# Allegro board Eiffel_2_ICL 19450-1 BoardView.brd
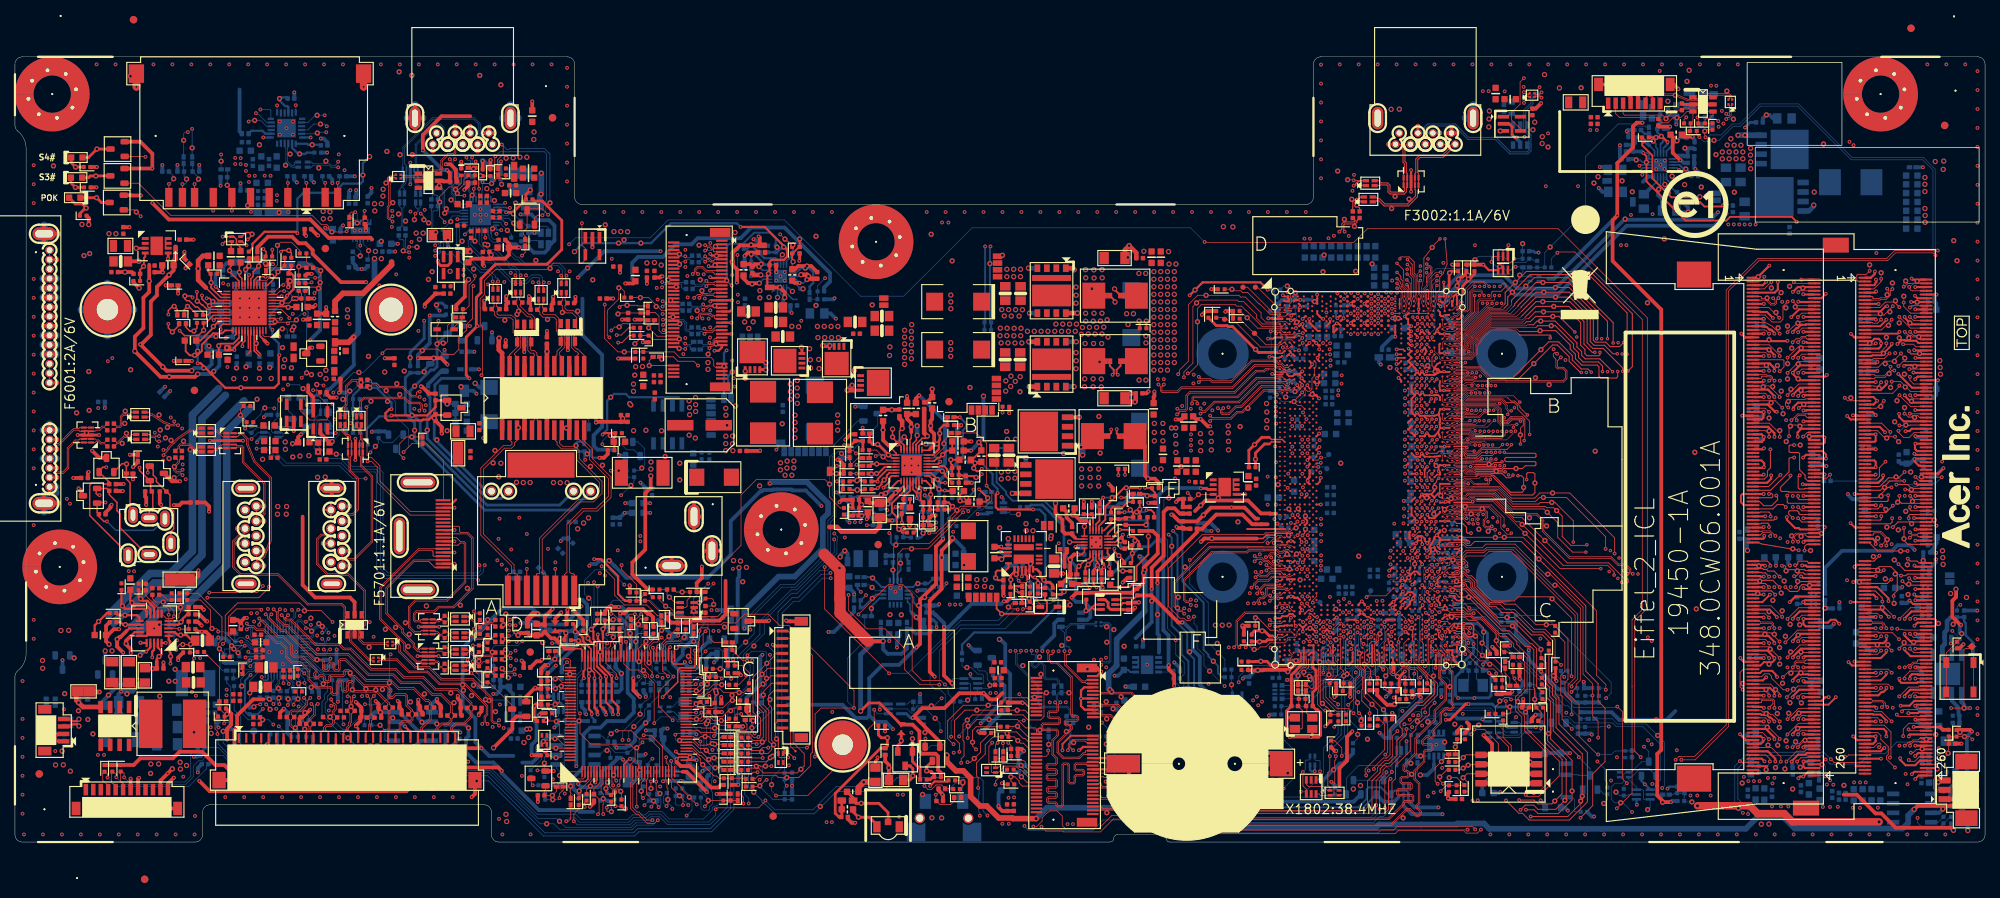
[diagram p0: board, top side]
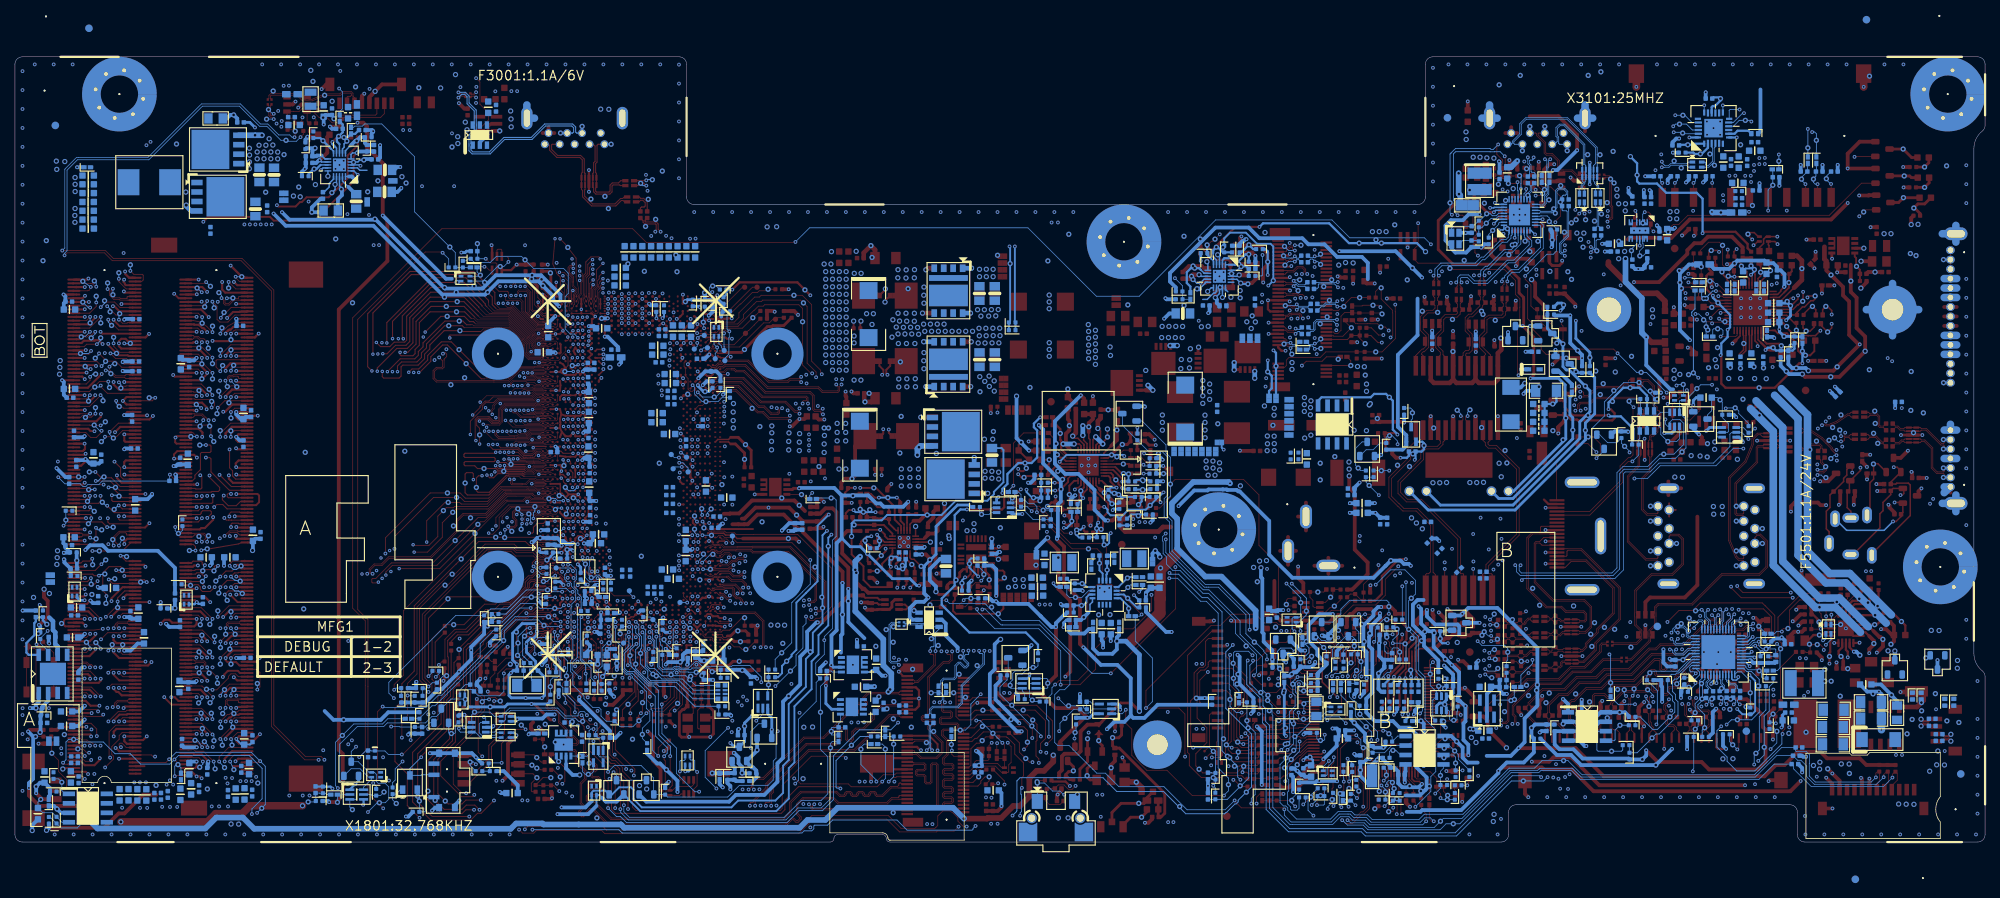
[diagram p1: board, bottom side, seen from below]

Outline 264 x 105.3 mm; copper layers: TOP, L2GND, L3, L4, L5GND, BOTTOM. Coordinates in mm from the lower left corner of the outline.
Outline path: 0,104.3 0,96.12 arc(0.1,95.69) 0.37,95.34 arc(1.2,94.3) 1.5,93 1.5,25.3 arc(1.2,24) 0.37,22.96 arc(0.1,22.61) 0,22.18 0,1 arc(0.29,0.29) 1,0 24.15,0 arc(24.86,0.29) 25.15,1 25.15,4 arc(25.44,4.71) 26.15,5 62.85,5 arc(63.56,4.71) 63.85,4 63.85,1 arc(64.14,0.29) 64.85,0 146.75,0 arc(147.1,0.15) 147.25,0.5 arc(147.4,0.85) 147.75,1 153.75,1 arc(154.1,0.85) 154.25,0.5 arc(154.4,0.15) 154.75,0 263,0 arc(263.71,0.29) 264,1 264,104.3 arc(263.71,105.01) 263,105.3 175,105.3 arc(174.29,105.01) 174,104.3 174,86.5 arc(173.71,85.79) 173,85.5 76,85.5 arc(75.29,85.79) 75,86.5 75,104.3 arc(74.71,105.01) 74,105.3 1,105.3 arc(0.29,105.01) 0,104.3

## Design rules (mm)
constraint set DEFAULT: min track width 0.127
net group AUD_W15_S10: nets CPVDD CPVEE
net group FAN_PWR_W20: nets FAN5V_OUT FAN5V_OUT_CONN
net group LPSS_UART2: nets LPSS_UART2_RXD LPSS_UART2_TXD
net group PCIE_RCOMP: nets PCIE_RCOMPN PCIE_RCOMPP
net group POWER_15_10: nets PROCHOT#_CPU PWR_VCORE_VCCST
net group POWER_20_20: nets PWR_VNN1D05V_BOOTA PWR_VNN1D05V_BOOTB
net group POWER_30_10: nets 3D3V_CARD 3D3V_S5_SPI
net group POWER_40_10: nets 3D3V_SIO_AVCC3 PWRLED_CON_5V
net group PWR_VCCAUX: nets PWR_VCCAUX_FSWEL PWR_VCCAUX_VOUT
net group RCOMP_W30_S12: nets EMMC_RCOMP XCLK_BIASREF
net group RTC: nets RTCRST_ON RTCRST_ON_R
net group SD_CLK: nets SD_CLK SD_CLK_1
net group TCRCOMP: nets TCRCOMP_DN TCRCOMP_DP
net group USB2_COMP: nets USB2_COMP USB_VBUSSENSE
net group 0D85V_S5: nets 0D85V_S5_VCCLDOSTD_OUT VCCIN_AUX_VID0 VCCIN_AUX_VID1 VCCST_OVERRIDE VCCST_OVERRIDE_N VCCSTPWRGOOD_TCSS
net group 50R_CNV_M_1: nets BT_PCMFRM_RSTN BT_PCMOUT_CLKREQ0 CNV_WT_RCOMP GPP_A8_SFRM GPP_A9_CLKREQ0
net group 50R_CNVI_W4_S20: nets CNV_BRI_DT CNV_BRI_DT_R CNV_BRI_RSP CNV_BRI_RSP_R CNV_RGI_DT CNV_RGI_DT_R CNV_RGI_RSP CNV_RGI_RSP_R
net group AUD_ANALOG_W8_S15: nets 3V_MIC2V AUD_HP1_JACK_L1 AUD_HP1_JACK_L2 AUD_HP1_JACK_L2_R AUD_HP1_JACK_R1 AUD_HP1_JACK_R2 AUD_HP1_JACK_R2_R AUD_HP1_JD# AUD_HP1_JD#_TYPE AUD_SENSE_A LINE1_L LINE1_R LINE1_VREFO_L LINE1_VREFO_R RING2 SELEEVE
net group AUD_DMIC_W4_S8: nets CODEC_I2C_SCL_DMIC_L CODEC_I2C_SCL_DMIC_R CODEC_I2C_SDA_DMIC_L CODEC_I2C_SDA_DMIC_R DMIC1_DATA_CON DMIC_CLK_CON DMIC_CLK_DMIC1 DMIC_DATA_DMIC1
net group AUD_W10_S10: nets CBN CBP LDO1_CAP LDO2_CAP LDO3_CAP MIC_CAP
net group AUD_W25_S8: nets AUDIO_VREF
net group CFG_RCOMP: nets CFG_RCOMP
net group CHGR_PSYS_IMVP: nets CHGR_PSYS_IMVP
net group CPU_POPI_RCOMP: nets CPU_POPI_RCOMP
net group CSI_RCOMP: nets CSI_RCOMP
net group DDR4_A_CMD: nets M_A_A0 M_A_A1 M_A_A2 M_A_A3 M_A_A4 M_A_A5 M_A_A6 M_A_A7 M_A_A8 M_A_A9 M_A_A10 M_A_A11 M_A_A12 M_A_A13 M_A_A14 M_A_A15 M_A_A16
net group DDR4_A_CNT: nets M_A_ACT_N M_A_ALERT_N M_A_BA0 M_A_BA1 M_A_BG0 M_A_BG1 M_A_CKE0 M_A_CKE1 M_A_CS#0 M_A_CS#1 M_A_ODT0 M_A_ODT1 M_A_PARITY
net group DDR4_A_DATA0: nets M_A_DQ0 M_A_DQ1 M_A_DQ2 M_A_DQ3 M_A_DQ4 M_A_DQ5 M_A_DQ6 M_A_DQ7
net group DDR4_A_DATA1: nets M_A_DQ8 M_A_DQ9 M_A_DQ10 M_A_DQ11 M_A_DQ12 M_A_DQ13 M_A_DQ14 M_A_DQ15
net group DDR4_A_DATA2: nets M_A_DQ16 M_A_DQ17 M_A_DQ18 M_A_DQ19 M_A_DQ20 M_A_DQ21 M_A_DQ22 M_A_DQ23
net group DDR4_A_DATA3: nets M_A_DQ24 M_A_DQ25 M_A_DQ26 M_A_DQ27 M_A_DQ28 M_A_DQ29 M_A_DQ30 M_A_DQ31
net group DDR4_A_DATA4: nets M_A_DQ32 M_A_DQ33 M_A_DQ34 M_A_DQ35 M_A_DQ36 M_A_DQ37 M_A_DQ38 M_A_DQ39
net group DDR4_A_DATA5: nets M_A_DQ40 M_A_DQ41 M_A_DQ42 M_A_DQ43 M_A_DQ44 M_A_DQ45 M_A_DQ46 M_A_DQ47
net group DDR4_A_DATA6: nets M_A_DQ48 M_A_DQ49 M_A_DQ50 M_A_DQ51 M_A_DQ52 M_A_DQ53 M_A_DQ54 M_A_DQ55
net group DDR4_A_DATA7: nets M_A_DQ56 M_A_DQ57 M_A_DQ58 M_A_DQ59 M_A_DQ60 M_A_DQ61 M_A_DQ62 M_A_DQ63
net group DDR4_B_CMD: nets M_B_A0 M_B_A1 M_B_A2 M_B_A3 M_B_A4 M_B_A5 M_B_A6 M_B_A7 M_B_A8 M_B_A9 M_B_A10 M_B_A11 M_B_A12 M_B_A13 M_B_A14 M_B_A15 M_B_A16
net group DDR4_B_CNT: nets M_B_ACT_N M_B_ALERT_N M_B_BA0 M_B_BA1 M_B_BG0 M_B_BG1 M_B_CKE0 M_B_CKE1 M_B_CS#0 M_B_CS#1 M_B_ODT0 M_B_ODT1 M_B_PARITY
net group DDR4_B_DATA0: nets M_B_DQ0 M_B_DQ1 M_B_DQ2 M_B_DQ3 M_B_DQ4 M_B_DQ5 M_B_DQ6 M_B_DQ7
net group DDR4_B_DATA1: nets M_B_DQ8 M_B_DQ9 M_B_DQ10 M_B_DQ11 M_B_DQ12 M_B_DQ13 M_B_DQ14 M_B_DQ15
net group DDR4_B_DATA2: nets M_B_DQ16 M_B_DQ17 M_B_DQ18 M_B_DQ19 M_B_DQ20 M_B_DQ21 M_B_DQ22 M_B_DQ23
net group DDR4_B_DATA3: nets M_B_DQ24 M_B_DQ25 M_B_DQ26 M_B_DQ27 M_B_DQ28 M_B_DQ29 M_B_DQ30 M_B_DQ31
net group DDR4_B_DATA4: nets M_B_DQ32 M_B_DQ33 M_B_DQ34 M_B_DQ35 M_B_DQ36 M_B_DQ37 M_B_DQ38 M_B_DQ39
net group DDR4_B_DATA5: nets M_B_DQ40 M_B_DQ41 M_B_DQ42 M_B_DQ43 M_B_DQ44 M_B_DQ45 M_B_DQ46 M_B_DQ47
net group DDR4_B_DATA6: nets M_B_DQ48 M_B_DQ49 M_B_DQ50 M_B_DQ51 M_B_DQ52 M_B_DQ53 M_B_DQ54 M_B_DQ55
net group DDR4_B_DATA7: nets M_B_DQ56 M_B_DQ57 M_B_DQ58 M_B_DQ59 M_B_DQ60 M_B_DQ61 M_B_DQ62 M_B_DQ63
net group DDR4_RCOMP_15: nets SM_RCOMP_0 SM_RCOMP_1 SM_RCOMP_2
net group DISP_RCOMP: nets DISP_RCOMP
net group EC_VFSPI: nets EC_VFSPI
net group ECIO_HW_S10: nets SIO_VREF SYS_TMPIN1 VRD_TMPIN2
net group ECIO_W4_S10: nets E51_RXD E51_TXD E51_TXD_EC E51_TXD_R EAPD# LDRQ# PB_IN_N_1 PWRBTN# PWRBTN#_1 PWRBTN_IN SIO_AUDIO_MUTE SIO_CE_N SIO_CLK_DB SIO_DAT_DB SIO_HOLD# SIO_SCK SIO_SCK_R SIO_SI SIO_SO SIO_WP# SIO_WRST#
net group ESPI_AD_CPU: nets ESPI_CON_ALERT# ESPI_CPU_CLK ESPI_CPU_CLK_DBG ESPI_CPU_CLK_EC ESPI_CPU_CS# ESPI_CPU_CS#_DB ESPI_CPU_CS#_EC ESPI_CPU_IO0 ESPI_CPU_IO0_DB ESPI_CPU_IO0_EC ESPI_CPU_IO1 ESPI_CPU_IO1_DB ESPI_CPU_IO1_EC ESPI_CPU_IO2 ESPI_CPU_IO2_DB ESPI_CPU_IO2_EC ESPI_CPU_IO3 ESPI_CPU_IO3_DB ESPI_CPU_IO3_EC ESPI_CPU_RST# ESPI_EC_ALERT# ESPI_EC_ALERT#_CPU
net group FAN_CTRL_W4_S15: nets CPU_FAN_CTRL CPU_FAN_CTRL_SIO CPU_FAN_TACH_SIO
net group HDA_W5_S10: nets HDA_BITCLK_CODEC HDA_BITCLK_CPU HDA_RST_N_CODEC HDA_RST_N_CODEC_R HDA_RST_N_CPU HDA_SDIN0_CODEC HDA_SDIN0_CPU HDA_SDOUT_CODEC HDA_SDOUT_CPU HDA_SPKR HDA_SYNC_CODEC HDA_SYNC_CPU
net group HDMI_DDC_W4_S10: nets HDMI1_DDCCLK_CON HDMI1_DDCDATA_CON HDMI_SCL_CPU HDMI_SDA_CPU
net group LAN_CLK: nets LAN_XTAL1 LAN_XTAL2 LAN_XTAL2_R
net group LAN_XF: nets XRF_TDC1
net group LED_W15_S10: nets LAN_EESK LAN_LED_ACTIVE LAN_LINK_100 LAN_LINK_1000 LAN_LINK_N LED2_N LED2_P LED9_N LED9_P LED10_N LED10_P PWRLED_CON SPEED_100_L1 SPEED_1000_L1 SUSLED_1 SUSLED_2 SUSLED_CON SUSLED_CON_OR SUSLED_CON_P1 V_5_LED
net group LPC_CLK: nets SIO_PCICLK
net group LVDS_W4_S8: nets BKLT_ADJ BKLT_ADJ_PWM BKLT_EN BKLT_EN_EC BKLT_EN_ENA DP_REXT DP_VARY_BL_R LCD_5V_ON1 MODE_CFG0 MODE_CFG1 PS8625_BKLT_EN PS8625_BKLT_PWM PS8625_LCD_PW_EN RTL_ISOLATE_N TEST_MODE
net group MISC_4_9: nets LAN_WAKE# LAN_WAKE#_R LAN_WAKEB MINI1_WAKE# PCIE_WAKE# SSD_WAKE# THERMAL_SHUT#
net group OCP: nets 65W_OCP IMON_VIN IMON_VIN_N IMON_VIN_P IMON_VOUT IMON_VOUT_Q5 IMON_VOUT_R1 IMON_VOUT_R1_G PSYS
net group OTHER_4: nets BIOS_REC D4302_PIN3 DBG_PMODE GSPI_MOSI PCH_PWROK_R PCH_THERMTRIP PM_BATLOW# PMCALERT# PROC_TCK PROC_TDI PROC_TMS PROC_TRST# RSVD RTC_INTRUDER# SATAXPCIE1 SVID_ALERT#_CPU_R
net group PANEL_4_10: nets PWR_ID0 PWR_ID1 PWR_ID2
net group PCH_RCOMP: nets PCH_OPI_RCOMP
net group POWER_10_10: nets PWR_1D8V_VFB PWR_1D8V_VFB_A PWR_3D3V_FB2_A PWR_VCCAUX_PG PWR_VCORE_CLK PWR_VCORE_DATA PWR_VCORE_FB PWR_VCORE_IMON PWR_VCORE_PSYS PWR_VCORE_SET1 PWR_VCORE_SET1_A PWR_VCORE_SET1_B PWR_VCORE_SET2 PWR_VCORE_SET2_A PWR_VCORE_SET2_B PWR_VCORE_SET3 PWR_VCORE_SET3_A PWR_VCORE_SET3_B PWR_VCORE_VIN PWR_VNN1D05V_PG1 PWR_VNN1D05V_PG2 PWR_VNN1D05V_VID
net group POWER_10_15: nets PWR_1D8V_PFM PWR_1D8V_SS PWR_VCCAUX_COMP PWR_VCCAUX_COMPA PWR_VCCAUX_COMPB PWR_VCCAUX_CS_DIS PWR_VCCAUX_FB PWR_VCCAUX_ISENSEP PWR_VCCAUX_NTC PWR_VCCAUX_VID0 PWR_VCCAUX_VID1 PWR_VCCAUX_VOUTA PWR_VCCAUX_VSYS PWR_VCORE_ISEN1N PWR_VCORE_ISEN1P PWR_VCORE_ISEN1P_B PWR_VCORE_ISEN2N PWR_VCORE_ISEN2P PWR_VCORE_ISEN2P_B PWR_VCORE_NTC1N PWR_VCORE_NTC1N_A PWR_VCORE_NTC1P PWR_VCORE_RGND PWR_VCORE_TSEN PWR_VCORE_TSEN_A PWR_VCORE_TSEN_A_A PWR_VCORE_VREF PWR_VCORE_VREF_A PWR_VCORE_VSEN PWR_VNN1D05V_FB2 PWR_VNN1D05V_VOUT1
net group POWER_12_10: nets 1D8V_AUDIO_S0 1D8V_S5_PWRGD 3D3V_SB_SYS 5V_AUX_S5 19V_ADP_GATE HDMI_SCL_R HDMI_SDA_R PROCHOT#_CPU_R PWR_1D8V_PG PWR_2D5V_EN PWR_3D3V_5V_PG PWR_3D3V_CS2 PWR_5V_CS1 PWR_ISET PWR_LPF PWR_MCT1_R PWR_RT PWR_SSTCMP PWR_SSTCMP_1 PWR_STATUS PWR_VCCAUX_EN PWR_VCORE_COMP PWR_VCORE_VR_READY PWR_VDDQ_CS PWR_VDDQ_EN PWR_VDDQ_PG PWR_VDDQ_TON PWR_VTT_EN VCORE_PWRGD
net group POWER_20_10: nets 1D2V_VCCPLL_OC 1D05V_S5_BYPASS 1D05V_VCCIO_OUT 1D05V_VCCSTG_OUT_FUSE 1D05V_VCCSTG_OUT_LGC 1D05V_VNN_BYPASS 1D8V_S5_CLKLDO 1D8V_S5_CLKLDO_R 1D24V_S5_VCCDPHY_OUT 3D3V_RTC_PWR 3D3V_RTC_VCC 3D3V_SB_RTC 3D3V_VBAT_SIO 5V_PVDD2 5V_STB 5V_SUS1 19V_BOOST_SNB PWR_1D8V_TON PWR_3D3V_BOOT2 PWR_3D3V_BOOT2_A PWR_5V_BOOT1 PWR_5V_BOOT1_A PWR_DDR_SN PWR_VCCAUX_PVCC PWR_VCCAUX_VCC PWR_VCORE_BOOTA PWR_VCORE_BOOTA_A PWR_VCORE_BOOTB PWR_VCORE_BOOTB_A PWR_VCORE_VCC PWR_VDDQ_BOOT PWR_VDDQ_BOOT_A PWR_VNN1D05V_VCC
net group POWER_25_20: nets 19V_BOOST_LDR 19V_BOOST_LDR_R PWR_VCCAUX_LG PWR_VCORE_LGA PWR_VCORE_LGB
net group POWER_30_20: nets PWR_1D8V_BT
net group POWER_30_30: nets PWR_VDDQ_LG
net group POWER_40_12: nets V_SMA_VREF_CA V_SMA_VREF_CA_C V_SMB_VREF_CA V_SMB_VREF_CA_C
net group POWER_80: nets 1D05V_S5_VCCDSW_OUT
net group POWER_300: nets PWR_2D5V_FB PWR_3D3V_FB2 PWR_5V_BYP1 PWR_5V_FB1 PWR_5V_FB1_A PWR_5V_LDO5 PWR_VCORE_PVCC PWR_VDDQ_FB PWR_VDDQ_VDD PWR_VDDQ_VDDQ PWR_VDDQ_VID PWR_VDDQ_VTTREF
net group POWER_400: nets 3D3V_DB1
net group PWR_5V_3D3V_EN: nets 1D8V_S0_EN PWR_3D3V_EN2 PWR_5V_EN1
net group PWR_20_20: nets 19V_BOOST_ISW 19V_DCBATOUT_LCD_VIN PWR_ISEN1 PWR_ISEN2 PWR_ISEN3 PWR_ISEN4 PWR_VREF
net group PWR_VNN1D05V_BOOT: nets PWR_VCCAUX_BOOTA PWR_VNN1D05V_BOOTA_A PWR_VNN1D05V_BOOTB_A
net group SD_W4_S10: nets SD_CD_N# SD_CMD SD_DATA0 SD_DATA0_1 SD_DATA1 SD_DATA1_1 SD_DATA2 SD_DATA3 SD_WP
net group SD_W12_S12: nets AV18 CR_PE_REXT SD3_RCOMP SDREG
net group SEQUENCE_W4_S10: nets 1D05V_VCCST_EN 1D05V_VCCSTG_EN 1D05V_VCCSTG_EN_R 1D8V_FCH_C10_EN 2D5V_S3_EN 2D5V_S3_EN_EC 2D5V_S3_PWRGD 3V_5V_PWRGD 5V_3D3V_S0_ON 5V_FANCTL1_FSM# AC_PRESENT ALL_SYS_PWRGD AUDIO_PC_BEEP AUDIO_PC_BEEP255 AUDIO_PC_BEEP256 AUDIO_PC_BEEP_R BT_DISABLE_N CNVI_EN# CPU_C10_GATE# CPU_C10_GATE#_EC DDR_VTT_CNTL_L1 DDR_VTT_CNTL_L2 DDR_VTT_CNTL_L3 DEVSLP2 DEVSLP2_CON EC_AUDIO_MUTE EC_DTR2#_PH EC_EUP EC_EUP_EN EC_EUP_EN# EC_SCI# EC_SMI# EC_SMI#_R ECIO_RSMRST# EDP_BLCTRL_CPU EDP_BLEN_CPU EDP_HPD_CPU EDP_VDDEN_CPU EUP_DSW_SEL EXT_PWR_GATE# EXT_PWR_GATE#_R H_CATERR# H_RCIN# HDMI1_HPD_C HDMI1_HPD_CON HDMI1_LS_R HDMI_DET_CPU HPGP_M2_SATA_DET# ICH_RSMRST_N_R INPUT3VSEL JP1 KBDATA LAN_CLKREQ_CPU_N LAN_CLKREQ_CPU_N_C LAN_RSET LPC_PME# LVDS1_PIN4_PD ME_CNTL1 ME_CNTL2 ME_UNLOCK MINI_CLKREQ#_WLAN_C PCH_D1_SST PCH_DPWROK PCH_DPWROK_EC PCH_DPWROK_R PCH_JTAG_TCK PCH_JTAG_TDO PCH_PWROK PCH_PWROK_C_1 PCH_PWROK_C_2 PCH_PWROK_C_3 PCH_RTCRST_DOWN PCIRST1# PCIRST2# PCIRST_LAN# PECI_EC PECI_EC_R PLT_RST# PLT_RST_N_SSD PLT_WLAN_RST# PLTRST_LAN_N PLTRST_N_SIO PLTRST_SSD PM_CLKRUN#_EC PM_CLKRUN#_EC_R PM_PWRBTN# PM_RSMRST# PM_SLP_S0# PM_SLP_S3# PM_SLP_S3_N PM_SLP_S4# PM_SLP_S4_N PM_SLP_SUSB# PM_SLP_SUSB#_ECIO PROCHOT_N_CPU PROCHOT_N_EC PROCHOT_N_OCP PROCHOT_N_OCP_R PS8625_HPD_R PWR_1D05V_EN PWR_1D8V_EN PWR_1D8V_EN_R PWR_VCORE_VR_EN PWR_VNN_EN PWRGD_PS_L PWRGD_PS_L1 PWROK3_1 PWROK3_1_R Q4002_2 Q4002_6 Q9639_AB_EC RSMRST_PWRGD# RSMRST_PWRGD#_ECIO RTC_DET# RTC_RST# RTC_RST#_R SA1_DIMB SE_BJT_B1 SE_BJT_B2 SE_BJT_B3 SE_VPP_EN_B SE_VTT_EN SIO_ATXPG SIO_BOARD_ID1 SIO_BOARD_ID2 SIO_BOARD_ID3 SIO_COPEN# SIO_DEBUG_RX SIO_DEBUG_TX SIO_GP17 SIO_K8PWR_EN SIO_PSON_N SIO_PSON_N_1 SM_DRAMRST# SM_DRAMRST#_CPU SM_PGCNTL SML1ALERT SRTC_RST# SSD1_CLKREQ_CPU_N SSD_CLKREQ# SUSLED_N SW_ON_N_SIO SYS_PWROK SYS_RESET# TBT_LSX0_RXD TBT_LSX1_RXD TBT_LSX2_RXD TBT_LSX3_RXD TP_CPU_PWRGD TP_DA11 TP_ISP_0 TP_ISP_1 TP_ISP_TRIG_0 TP_ISP_TRIG_1 TP_PCH_IST_1 TP_PROC_SELECT# TP_SKTOCC# TS#_DIMM1_0 TS#_DIMM1_1 USB_EN USB_EN_FRONT USB_EN_REAR USB_ID USB_OC# USB_SIO_EUP USB_SIO_EUP_R V12 V33 VCCST_EN VCCST_PWRGD VCCST_PWRGD_R VCORE_EN VCORE_EN_EC VDDQ_EN VDDQ_EN_EC VRALERT# VTT_CT_3D3V_S0 VTT_CT_5V_S0 W_DISABLE#2 W_DISABLE#2_CON WIFI_DISABLE_N WLAN_CLKREQ_CPU#
net group SINGLE_ENDED_CLK: nets PCH_SUSCLK_WLAN SUS_CLK_CPU SUSCLK_SSD
net group SIO_HM_12: nets HM_VCCP HM_VCCP_R SIO_MAIN_VCC3 SIO_VCORE SIO_VIN1 SIO_VIN2 SIO_VIN3 SIO_VIN4 SIO_VIN5
net group SMBUS_4_12: nets CPU_SMB_SCL CPU_SMB_SCL_DDR CPU_SMB_SCL_P0 CPU_SMB_SCL_P1 CPU_SMB_SCL_WLAN CPU_SMB_SDA CPU_SMB_SDA_DDR CPU_SMB_SDA_P0 CPU_SMB_SDA_P1 CPU_SMB_SDA_WLAN EC_SMB_SCL EC_SMB_SCL_OZ EC_SMB_SCL_OZ_C EC_SMB_SCL_TSMT EC_SMB_SDA EC_SMB_SDA_OZ EC_SMB_SDA_OZ_C EC_SMB_SDA_TSMT TSMT_SMB_SCL_U TSMT_SMB_SCL_U_R TSMT_SMB_SDA_U TSMT_SMB_SDA_U_R
net group SNDW_RCOMP: nets SNDW_RCOMP
net group SPI_4_S10: nets BOOT_HALT SPI_CLK_ROM SPI_CLK_ROM_R SPI_CS_CPU_N0 SPI_HOLD_ROM SPI_HOLD_ROM_R SPI_SI_ROM SPI_SI_ROM_R SPI_SO_ROM SPI_SO_ROM_R SPI_WP_R_N SPI_WP_ROM SPI_WP_ROM_R
net group STRAP_PIN_W5_S6: nets GPD_7 GPP_C2/SMBALERT# GPP_C5 GPP_E6_JTAG_ODT GPP_H0 GPP_H2
net group SVID_4_20: nets PWR_VCORE_ALERT# SVID_ALERT#_CPU SVID_CLK_CPU SVID_DATA_CPU
net group XDP_W4_S6: nets CFG0 CFG4 XDP_PRDY# XDP_PREQ#
net group XTAL_W4_S15: nets XTL_32K_X1_CPU XTL_32K_X2_CPU XTL_38D4M_X1_CPU XTL_38D4M_X1_CPU_R XTL_38D4M_X2_CPU XTL_38D4M_X2_CPU_R

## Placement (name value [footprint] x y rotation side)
AUDS1  AUDIO-JK645-GP  [J1100D-C6DH-0002R]  18 41.05 0 top
BTT1  BAT-40-42087-00211RHF-WH-GP-U1  [40-42087-00211RHF-WH-U1]  163.47 10.5 0 top
C501  SCD1U16V2KX-L-GP  [C402H22]  256.73 48.49 0 bottom
C701  SCD1U25V2KX-GP  [C402H22]  182.63 36.05 180 bottom
C702  SC100P50V2JN-3GP  [C402H22]  181.56 36.05 180 bottom
C703  SC12P50V2JN-3GP  [C402H24]  186.93 45.3 0 bottom
C1101  SC10U6D3V3MX-GP  [C603H38]  168.62 46.19 270 bottom
C1102  SC1U10V2KX-1GP  [C402H22]  187.2 61.9 180 bottom
C1103  SC1U10V2KX-1GP  [C402H22]  186.36 63.81 180 bottom
C1104  SC1U10V2KX-1GP  [C402H22]  187.25 63.81 180 bottom
C1105  SC1U10V2KX-1GP  [C402H22]  187.15 54.63 0 bottom
C1106  SC1U10V2KX-1GP  [C402H22]  186.98 49.91 0 bottom
C1107  SC1U10V2KX-1GP  [C402H22]  192.61 42.29 180 bottom
C1108  SC47U4V3MX-GP  [C603H40]  171.41 47.75 180 bottom
C1109  SC10U6D3V3MX-GP  [C603H38]  187.09 56.93 180 bottom
C1110  SC10U6D3V3MX-GP  [C603H38]  187.04 47.6 180 bottom
C1111  SC10U6D3V3MX-GP  [C603H38]  187.16 52.29 180 bottom
C1112  SC10U6D3V3MX-GP  [C603H38]  256.69 71.41 270 bottom
C1113  SC10U6D3V3MX-GP  [C603H38]  187.09 59.61 0 bottom
C1114  SC1U10V2KX-1GP  [C402H22]  191.68 40.31 180 bottom
C1115  SC1U10V2KX-1GP  [C402H22]  192.61 40.33 180 bottom
C1116  SC22U6D3V3MX-1-GP  [C603H40]  192.53 68.45 0 bottom
C1117  SC22U6D3V3MX-1-GP  [C603H40]  254.18 82.27 270 bottom
C1118  SC22U6D3V3MX-1-GP  [C603H40]  193.2 65.69 90 bottom
C1119  SC1U10V2KX-1GP  [C402H22]  159.47 42.32 180 bottom
C1120  SC1U10V2KX-1GP  [C402H22]  158.5 42.32 180 bottom
C1121  SC1U10V2KX-1GP  [C402H22]  156.51 42.55 0 top
C1122  SC1U10V2KX-1GP  [C402H22]  169.96 43.65 270 bottom
C1125  SC1U10V2KX-1GP  [C402H22]  183.63 66.03 90 bottom
C1126  SC1U10V2KX-1GP  [C402H22]  156.52 44.49 180 top
C1127  SC1U10V2KX-1GP  [C402H22]  157.4 44.49 180 top
C1128  SC1U10V2KX-1GP  [C402H22]  233.37 53.42 0 bottom
C1129  SC1U10V2KX-1GP  [C402H22]  233.86 69.23 270 bottom
C1205  SC10U6D3V3MX-L-GP  [C603H38]  247.89 45.22 0 bottom
C1206  SC10U6D3V3MX-L-GP  [C603H38]  246.71 27.38 180 bottom
C1207  SC10U6D3V3MX-L-GP  [C603H38]  256.74 40.87 270 bottom
C1208  SC10U6D3V3MX-L-GP  [C603H38]  251.2 34.08 270 bottom
C1209  SC10U6D3V3MX-L-GP  [C603H38]  247.46 30.71 180 bottom
C1213  SC10U6D3V3MX-L-GP  [C603H38]  255.74 31.45 90 bottom
C1214  SC10U6D3V3MX-L-GP  [C603H38]  253.48 51.52 180 bottom
C1215  SC10U6D3V3MX-L-GP  [C603H38]  256.69 60.77 270 bottom
C1216  SC1U10V2KX-1GP  [C402H22]  255.5 22.23 0 bottom
C1217  SC1U10V2KX-1GP  [C402H22]  256.8 39.81 270 bottom
C1218  SC1U10V2KX-1GP  [C402H22]  256.78 72.47 270 bottom
C1219  SC1U10V2KX-1GP  [C402H22]  256 30.4 90 bottom
C1220  SC1U10V2KX-1GP  [C402H22]  248.52 30.53 180 bottom
C1221  SCD022U16V2KX-3GP  [C402H22]  256.11 36.68 90 bottom
C1222  SC1U10V2KX-1GP  [C402H22]  256.62 59.59 270 bottom
C1223  SC1U10V2KX-1GP  [C402H22]  248.3 56.83 0 bottom
C1232  SC10U6D3V3MX-L-GP  [C603H38]  247.59 6.33 180 bottom
C1234  SC10U6D3V3MX-L-GP  [C603H38]  249.97 6.33 180 bottom
C1235  SC1U10V2KX-1GP  [C402H22]  245.31 6.13 180 bottom
C1236  SC1U10V2KX-1GP  [C402H22]  244.43 6.14 180 bottom
C1237  SC1U10V2KX-1GP  [C402H22]  247.76 70.13 270 bottom
C1238  SC10U6D3V3MX-L-GP  [C603H38]  246.4 6.32 180 bottom
C1250  SC10U6D3V3MX-L-GP  [C603H38]  248.78 6.34 180 bottom
C1251  SC1U10V2KX-1GP  [C402H22]  256.01 10.61 270 bottom
C1252  SC1U10V2KX-1GP  [C402H22]  256.01 11.48 270 bottom
C1271  SCD1U16V2KX-L-GP  [C402H22]  243.52 6.39 180 bottom
C1272  SC2D2U10V3KX-L-GP  [C603H36]  241.83 6.4 180 bottom
C1281  SCD1U16V2KX-L-GP  [C402H22]  252.84 32.53 180 bottom
C1302  SCD1U16V2KX-L-GP  [C402H22]  238.82 32.38 180 bottom
C1312  SC10U6D3V3MX-L-GP  [C603H38]  238.38 38.19 90 bottom
C1313  SC10U6D3V3MX-L-GP  [C603H38]  235.19 38.19 270 bottom
C1314  SC1U10V2KX-1GP  [C402H22]  231.09 41.11 180 bottom
C1315  SC1U10V2KX-1GP  [C402H22]  232.36 57.45 180 bottom
C1316  SC10U6D3V3MX-L-GP  [C603H38]  241.96 20.87 0 bottom
C1317  SC10U6D3V3MX-L-GP  [C603H38]  233.28 13.84 180 bottom
C1318  SC10U6D3V3MX-L-GP  [C603H38]  241.77 64.14 0 bottom
C1319  SC1U10V2KX-1GP  [C402H22]  239.32 7.16 180 bottom
C1320  SC10U6D3V3MX-L-GP  [C603H38]  240.63 9.83 0 bottom
C1321  SC10U6D3V3MX-L-GP  [C603H38]  240.39 7.14 180 bottom
C1322  SC1U10V2KX-1GP  [C402H22]  238.23 9.51 0 bottom
C1325  SC100P50V2JN-3GP  [C402H22]  242.85 48.43 90 bottom
C1327  SC10U6D3V3MX-L-GP  [C603H38]  232.11 41.14 180 bottom
C1328  SCD022U16V2KX-3GP  [C402H22]  242.55 32.9 180 bottom
C1329  SC10U6D3V3MX-L-GP  [C603H38]  240.83 51.33 180 bottom
C1330  SC10U6D3V3MX-L-GP  [C603H38]  233.38 57.47 180 bottom
C1331  SC1U10V2KX-1GP  [C402H22]  240.66 64.14 0 bottom
C1332  SC1U10V2KX-1GP  [C402H22]  241.89 29.29 180 bottom
C1333  SC1U10V2KX-1GP  [C402H22]  240.77 20.98 0 bottom
C1334  SC1U10V2KX-1GP  [C402H22]  241.86 51.09 180 bottom
C1335  SC1U10V2KX-1GP  [C402H22]  232.87 24.7 270 bottom
C1336  SC1U10V2KX-1GP  [C402H22]  232.17 13.86 180 bottom
C1338  SCD1U16V2KX-L-GP  [C402H22]  235.45 6.52 180 bottom
C1339  SC2D2U10V3KX-L-GP  [C603H36]  234.42 6.43 180 bottom
C1340  SC1U10V2KX-1GP  [C402H22]  232.21 6.57 180 bottom
C1341  SC1U10V2KX-1GP  [C402H22]  233.67 9.75 0 bottom
C1342  SC10U6D3V3MX-L-GP  [C603H38]  233.24 6.45 180 bottom
C1343  SC10U6D3V3MX-L-GP  [C603H38]  232.64 9.85 0 bottom
C1701  SCD1U16V2KX-3GP  [C402H22]  192.43 25.59 270 bottom
C1705  SCD1U16V2KX-3GP  [C402H22]  201.18 22.81 90 top
C1801  SC18P50V2JC-GP  [C402H22]  194.35 22.99 90 bottom
C1802  SC18P50V2JC-GP  [C402H22]  196.28 22.99 270 bottom
C1805  SC15P50V2JN-2-GP  [C402H22]  173.46 18.23 90 top
C1806  SC15P50V2JN-2-GP  [C402H22]  171.49 18.23 270 top
C1820  SC1U10V2KX-1GP  [C402H22]  202.55 21.11 90 bottom
C1821  SC1U10V2KX-1GP  [C402H22]  202.05 20.2 90 bottom
C1823  SCD1U16V2KX-3GP  [C402H22]  209.43 14.98 180 bottom
C1904  SC33P50V2JN-3GP  [C402H22]  203.7 16.25 270 top
C2201  SC1U10V2KX-L1-GP  [C402H22]  135.38 9.8 0 bottom
C2202  SCD1U16V2KX-L-GP  [C402H22]  145.04 18.31 270 bottom
C2203  SC1U10V2KX-L1-GP  [C402H22]  184.15 30.71 270 bottom
C2204  SC1U10V2KX-1GP  [C402H22]  187.18 31.95 270 bottom
C2205  SC4D7U6D3V3KX-GP  [C603H36]  184.71 24.29 0 bottom
C2206  SC1U10V2KX-1GP  [C402H22]  185.04 29.8 90 bottom
C2207  SCD1U16V2KX-3GP  [C402H22]  185.56 28.39 180 bottom
C2208  SC1U10V2KX-L1-GP  [C402H22]  170.2 42.15 270 bottom
C2209  SC1U10V2KX-L1-GP  [C402H22]  134.48 9.79 0 bottom
C2210  SC1U10V2KX-L1-GP  [C402H22]  179.21 33.77 0 bottom
C2211  SC1U10V2KX-L1-GP  [C402H22]  177.4 33.75 0 bottom
C2212  SC1U10V2KX-L1-GP  [C402H22]  178.32 33.76 0 bottom
C2213  SC2D2U10V3KX-L-GP  [C603H36]  186.68 25.08 270 bottom
C2214  SCD1U16V2KX-L-GP  [C402H22]  145.04 17.41 270 bottom
C2215  SC1U10V2KX-1GP  [C402H22]  173.84 25.12 180 bottom
C2216  SC47U6D3V3MX-GP  [C603H40]  169.81 24.32 90 bottom
C2217  SCD1U25V2KX-GP  [C402H22]  174.07 53.52 180 bottom
C2218  SC100P50V2JN-3GP  [C402H22]  171.83 56.2 180 bottom
C2219  SC12P50V2JN-3GP  [C402H24]  176.07 58.71 270 bottom
C2401  SC2D2U10V3KX-1GP  [C603H36]  90.31 9.53 0 bottom
C2402  SCD1U16V2KX-3GP  [C402H22]  83.71 11.17 0 bottom
C2403  SC100P50V2JN-3GP  [C402H22]  95.89 6.02 180 top
C2404  SCD1U16V2KX-3GP  [C402H22]  79.46 24.89 180 bottom
C2405  SC22U6D3V3MX-1-GP  [C603H40]  69.9 28.49 180 top
C2406  SCD1U16V2KX-3GP  [C402H22]  92.95 9.42 0 bottom
C2407  SCD1U16V2KX-3GP  [C402H22]  77.75 20.59 180 bottom
C2408  SC22U6D3V3MX-1-GP  [C603H40]  95.94 30.53 0 bottom
C2409  SCD1U16V2KX-3GP  [C402H22]  75.92 20.6 180 bottom
C2410  SCD1U16V2KX-3GP  [C402H22]  86.17 14.97 90 bottom
C2411  SCD1U16V2KX-3GP  [C402H22]  79.64 20.6 180 bottom
C2412  SCD1U16V2KX-3GP  [C402H22]  70.51 6.26 90 top
C2413  SCD1U16V2KX-3GP  [C402H22]  78.81 18.36 0 bottom
C2414  SCD1U16V2KX-3GP  [C402H22]  80.54 20.59 180 bottom
C2415  SCD1U16V2KX-3GP  [C402H22]  91.35 9.45 180 bottom
C2416  SCD1U16V2KX-3GP  [C402H22]  78.2 9.03 90 bottom
C2417  SC100P50V2JN-3GP  [C402H22]  94.2 18.65 90 top
C2418  SC1U10V2KX-1GP  [C402H22]  86.42 25.14 90 bottom
C2419  SC1U10V2KX-1GP  [C402H22]  92.19 23.52 270 bottom
C2420  SC22U6D3V3MX-1-GP  [C603H40]  86.12 13.89 90 bottom
C2421  SC1U10V2KX-1GP  [C402H22]  80.06 23.48 270 bottom
C2422  SC1U10V2KX-1GP  [C402H22]  93.43 17.43 90 top
C2423  SC100P50V2JN-3GP  [C402H22]  77.59 6 0 top
C2424  SCD1U25V2KX-GP  [C402H22]  71.73 20.9 90 bottom
C2425  SC1U10V2KX-1GP  [C402H22]  71 28.62 180 top
C2426  SCD1U16V2KX-3GP  [C402H22]  94.91 30.55 0 bottom
C2427  SCD1U16V2KX-3GP  [C402H22]  80.69 27.8 270 bottom
C2501  SC10U6D3V3MX-L-GP  [C603H38]  197.39 6.57 270 bottom
C2502  SCD1U16V2KX-L-GP  [C402H22]  193.47 5.78 270 top
C2503  SCD1U25V2KX-GP  [C402H22]  167.57 8.8 180 bottom
C2507  SC1U10V2KX-1GP  [C402H22]  166.68 14.33 270 bottom
C2601  SC4D7U6D3V3KX-GP  [C603H36]  256.51 8.73 0 bottom
C2602  SCD1U16V2KX-3GP  [C402H22]  255.47 8.35 0 bottom
C2603  SC22U6D3V3MX-1-GP  [C603H40]  260.91 3.8 180 bottom
C2604  SC4D7U6D3V3KX-GP  [C603H36]  260.04 8.72 0 bottom
C2605  SC100P50V2JN-3GP  [C402H22]  259.57 13.19 90 top
C2701  SC4D7U6D3V3KX-L-GP  [C603H36]  28.32 69.72 270 bottom
C2702  SC10U6D3V3MX-L-GP  [C603H38]  26.67 77.34 270 top
C2703  SC2D2U10V3KX-L-GP  [C603H36]  23.52 67.25 270 top
C2704  SC2D2U10V3KX-L-GP  [C603H36]  28.32 72.26 90 bottom
C2705  SC2D2U10V3KX-L-GP  [C603H36]  26.67 78.61 270 top
C2706  SC10U6D3V3MX-GP  [C603H38]  31.32 64.76 180 bottom
C2707  SCD1U16V2KX-L-GP  [C402H22]  29.72 64.64 180 bottom
C2708  SC10U6D3V3MX-GP  [C603H38]  34.24 64.76 180 bottom
C2709  SCD1U16V2KX-L-GP  [C402H22]  32.78 64.63 180 bottom
C2710  SCD1U16V2KX-L-GP  [C402H22]  27.89 76.23 180 bottom
C2711  SC10U6D3V3MX-GP  [C603H38]  29.29 76.95 180 bottom
C2712  SC10U6D3V3MX-L-GP  [C603H38]  26.57 65.36 90 top
C2713  SC10U6D3V3MX-L-GP  [C603H38]  32.43 75.8 180 bottom
C2714  SC10U6D3V3MX-L-GP  [C603H38]  28.32 70.99 270 bottom
C2715  SC4D7U6D3V3KX-L-GP  [C603H36]  28.5 65.43 0 top
C2716  SCD1U16V2KX-L-GP  [C402H22]  39.46 69.72 180 top
C2717  SC10U6D3V3MX-L-GP  [C603H38]  41.71 70.07 180 top
C2718  SC10U6D3V3MX-L-GP  [C603H38]  38.48 71.75 90 top
C2719  SCD1U16V2KX-L-GP  [C402H22]  36.67 75.79 180 top
C2720  SC10U6D3V3MX-L-GP  [C603H38]  40.5 70.1 180 top
C2723  SC4D7U6D3V3KX-L-GP  [C603H36]  28.96 78.49 180 top
C2724  SC4D7U6D3V3KX-L-GP  [C603H36]  30.23 78.49 180 top
C2725  SCD1U16V2KX-L-GP  [C402H22]  39.51 77.01 270 top
C2726  SC33P50V2JN-3GP  [C402H22]  38.83 72.89 90 top
C2907  SCD1U16V2KX-3GP  [C402H22]  9.33 48.83 270 top
C2908  SCD1U16V2KX-3GP  [C402H22]  23.98 45.54 90 top
C2910  SCD1U16V2KX-3GP  [C402H22]  19.72 60.03 225 bottom
C2911  SC2200P50V2KX-2GP  [C402H22]  11.6 59.02 90 bottom
C3001  SCD01U50V2KX-1GP  [C402H22]  211.18 96.76 0 top
C3002  SCD1U16V2KX-3GP  [C402H22]  212.07 96.75 0 top
C3004  SC22U6D3V3MX-1-GP  [C603H40]  222.63 98.04 180 bottom
C3005  SCD1U16V2KX-3GP  [C402H22]  221.51 97.94 180 bottom
C3006  SCD1U16V2KX-3GP  [C402H22]  226.94 97.21 270 bottom
C3007  SC4D7U6D3V3KX-GP  [C603H36]  226.59 96.16 270 bottom
C3008  SC10P50V2JN-4GP  [C402H22]  220.23 96.54 0 top
C3009  SC10P50V2JN-4GP  [C402H22]  223.37 98.6 180 top
C3102  SC4D7U6D3V3KX-GP  [C603H36]  66.42 87.03 90 top
C3103  SCD1U16V2KX-3GP  [C402H22]  66.69 88.07 90 top
C3106  SCD1U16V2KX-3GP  [C402H22]  65.06 89.35 0 bottom
C3118  SCD1U16V2KX-3GP  [C402H22]  63.58 78.68 0 top
C3119  SCD1U16V2KX-3GP  [C402H22]  62.69 78.68 0 top
C3125  SC1KP2KV6KX-GP  [C1206H71]  58.83 60.52 270 bottom
C3126  SC18P50V2JN-1-GP  [C402H22]  68.8 82.15 0 bottom
C3127  SC18P50V2JN-1-GP  [C402H22]  68.81 80.23 0 bottom
C3128  SCD1U16V2KX-3GP  [C402H22]  61.19 88.44 270 top
C3129  SCD1U16V2KX-3GP  [C402H22]  68.23 67.03 0 bottom
C3130  SCD1U16V2KX-3GP  [C402H22]  60.3 65.75 270 bottom
C3131  SCD1U16V2KX-3GP  [C402H22]  56.68 85.73 0 bottom
C3132  SCD1U16V2KX-3GP  [C402H22]  55.8 85.73 0 bottom
C3133  SCD1U16V2KX-3GP  [C402H22]  59.75 82.68 90 top
C3134  SCD1U16V2KX-3GP  [C402H22]  65.25 80.75 90 top
C3135  SC4D7U6D3V3KX-GP  [C603H36]  60.07 85.55 90 top
C3136  SC4D7U6D3V3KX-GP  [C603H36]  65.43 79.72 90 top
C3137  SCD1U16V2KX-3GP  [C402H22]  61.13 81.47 180 top
C3138  SCD1U16V2KX-3GP  [C402H22]  64.5 83.77 270 top
C3139  SCD1U16V2KX-3GP  [C402H22]  64.5 84.64 270 top
C3140  SCD1U16V2KX-3GP  [C402H22]  62.53 81.98 270 top
C3141  SC1U10V2KX-1GP  [C402H22]  62.35 86.2 0 top
C3142  SCD1U16V2KX-3GP  [C402H22]  63.23 86.2 0 top
C3143  SCD1U16V2KX-3GP  [C402H22]  74.08 67.27 0 bottom
C3145  SCD1U16V2KX-3GP  [C402H22]  61.27 88.81 0 bottom
C3146  SCD1U16V2KX-3GP  [C402H22]  60.41 88.81 0 bottom
C3147  SC4D7U6D3V3KX-GP  [C603H36]  64.03 89.73 0 bottom
C3151  SCD1U16V2KX-3GP  [C402H22]  71.28 67.26 180 top
C3152  SC1KP50V2KX-1GP  [C402H22]  65.28 66.48 90 top
C3153  SC22U6D3V3MX-1-GP  [C603H40]  60.76 78.51 0 top
C3154  SCD1U16V2KX-3GP  [C402H22]  56.34 73.98 0 top
C3155  SC1U10V2KX-1GP  [C402H22]  57.91 73.55 270 top
C3301  SC1U10V2KX-1GP  [C402H22]  36.99 99.7 270 bottom
C3302  SC1U10V2KX-1GP  [C402H22]  41.44 93.42 90 bottom
C3303  SC4D7U6D3V3KX-GP  [C603H36]  35.08 91.19 180 bottom
C3304  SCD1U16V2KX-3GP  [C402H22]  34.04 91.13 180 bottom
C3305  SC4D7U6D3V3KX-GP  [C603H36]  33.02 91.19 180 bottom
C3306  SCD1U16V2KX-3GP  [C402H22]  31.88 91.12 180 bottom
C3307  SC4D7U6D3V3KX-GP  [C603H36]  30.86 92.71 90 bottom
C3308  SCD1U16V2KX-3GP  [C402H22]  30.86 93.85 90 bottom
C3309  SC4D7U6D3V3KX-GP  [C603H36]  33.13 88.4 90 bottom
C3312  SCD1U16V2KX-3GP  [C402H22]  33.01 86.34 90 bottom
C3313  SCD1U16V2KX-3GP  [C402H22]  33.01 85.45 90 bottom
C3314  SCD1U16V2KX-3GP  [C402H22]  30.67 87.38 270 bottom
C3401  SCD1U50V3KX-GP  [C603H36]  37.38 59.6 270 bottom
C3404  SC22U6D3V3MX-1-GP  [C603H40]  34.07 55.87 270 top
C3405  SC1U10V2KX-1GP  [C402H22]  36.54 62.18 270 top
C3406  SCD1U16V2KX-3GP  [C402H22]  34.74 51.54 270 top
C3407  SC22U6D3V3MX-1-GP  [C603H40]  34.16 53.77 270 top
C3409  SC22U6D3V3MX-1-GP  [C603H40]  41.4 53.57 90 top
C3411  SCD1U16V2KX-3GP  [C402H22]  41.29 51.3 90 top
C3412  SCD1U16V2KX-3GP  [C402H22]  41.32 60.31 90 top
C3413  SCD1U16V2KX-3GP  [C402H22]  21.5 52.01 180 top
C3414  SCD1U16V2KX-3GP  [C402H22]  22.37 52.01 180 top
C3415  SCD1U16V2KX-3GP  [C402H22]  46.79 61.12 270 top
C3416  SCD1U16V2KX-3GP  [C402H22]  46.8 62 270 top
C3417  SC22U6D3V3MX-1-GP  [C603H40]  34.15 52.56 270 top
C3418  SC22U6D3V3MX-1-GP  [C603H40]  41.39 52.37 90 top
C3423  SC22U6D3V3MX-1-GP  [C603H40]  38.71 53.62 270 top
C3501  SCD22U10V2KX-1GP  [C402H22]  179.28 84.12 180 top
C3502  SCD22U10V2KX-1GP  [C402H22]  180.19 84.13 180 top
C3513  SCD1U16V2KX-3GP  [C402H22]  52.33 81.79 0 bottom
C3514  SCD1U16V2KX-3GP  [C402H22]  51.44 81.79 0 bottom
C3515  SC1U10V2KX-1GP  [C402H22]  80.63 77.18 90 top
C3516  SCD1U16V2KX-3GP  [C402H22]  58.74 88.59 90 top
C3517  SC22U6D3V3MX-1-GP  [C603H40]  69.32 97.36 180 top
C3518  SC22U6D3V3MX-1-GP  [C603H40]  68.82 90.3 270 top
C3520  SC22U6D3V3MX-1-GP  [C603H40]  68.82 89.11 270 top
C3521  SCD1U16V2KX-3GP  [C402H22]  199.53 98.41 0 bottom
C3522  SC22U6D3V3MX-1-GP  [C603H40]  198.41 100.37 180 top
C3523  SC22U6D3V3MX-1-GP  [C603H40]  200.36 99.61 90 top
C3524  SC1U10V2KX-1GP  [C402H22]  203.34 97.91 180 top
C3526  SC22U6D3V3MX-1-GP  [C603H40]  200.58 98.54 0 bottom
C4001  SCD1U16V2KX-3GP  [C402H22]  125.21 42.82 180 bottom
C4007  SC1KP50V2KX-1GP  [C402H22]  45.26 78.72 180 bottom
C4008  SC1KP50V2KX-1GP  [C402H22]  47.26 77.66 180 bottom
C4009  SC1U10V2KX-1GP  [C402H22]  44.76 86.05 0 bottom
C4011  SC10U6D3V3MX-GP  [C603H38]  42.6 81.45 0 bottom
C4012  SC1U10V2KX-1GP  [C402H22]  47.27 86.13 0 bottom
C4013  SCD1U16V2KX-3GP  [C402H22]  46.88 83.3 0 top
C4014  SC10U6D3V3MX-GP  [C603H38]  49.66 80.23 270 bottom
C4015  SC1U10V2KX-1GP  [C402H22]  189.9 16.03 90 bottom
C4016  SC1U10V2KX-1GP  [C402H22]  188.01 13.91 0 bottom
C4017  SC1U10V2KX-1GP  [C402H22]  45.64 86.05 0 bottom
C4018  SCD1U16V2KX-3GP  [C402H22]  147.6 18.23 180 bottom
C4019  SCD1U16V2KX-3GP  [C402H22]  150.69 26.24 270 bottom
C4020  SCD1U16V2KX-3GP  [C402H22]  166.32 48.26 180 top
C4024  SC1U10V2KX-1GP  [C402H22]  223.72 7.01 0 bottom
C4025  SCD1U16V2KX-3GP  [C402H22]  131.7 24.1 270 top
C4026  SCD1U16V2KX-3-LL-GP  [C402H22]  202.48 79.23 270 bottom
C4030  SCD1U16V2KX-L-GP  [C402H22]  165.38 21.71 0 bottom
C4048  SCD1U25V2KX-GP  [C402H22]  43.63 81.43 0 bottom
C4049  SCD1U25V2KX-GP  [C402H22]  49.69 79.19 270 bottom
C4053  SC10U6D3V3MX-GP  [C603H38]  148.67 18.21 180 bottom
C4060  SC10U6D3V3MX-GP  [C603H38]  148.59 23.84 180 bottom
C4061  SCD1U16V2KX-3DLGP  [C402H22]  155.66 22.93 270 bottom
C4062  SCD1U16V2KX-3DLGP  [C402H22]  153.18 15.38 90 bottom
C4069  SC1U10V2KX-1GP  [C402H22]  158.62 48.25 270 top
C4070  SC10U6D3V3MX-GP  [C603H38]  165.29 48.32 180 top
C4072  SCD1U16V2KX-3DLGP  [C402H22]  157.04 46.01 270 top
C4085  SC10U6D3V3MX-GP  [C603H38]  150.69 20.83 270 bottom
C4093  SC1U10V2KX-1GP  [C402H22]  157.94 42.02 270 top
C4302  SCD1U25V2KX-GP  [C402H22]  87.83 33.86 270 top
C4303  SCD1U25V2KX-GP  [C402H22]  92.53 31.21 0 top
C4304  SC1KP50V2KX-1GP  [C402H22]  76.76 52.37 270 bottom
C4501  SCD1U16V2KX-3GP  [C402H22]  105.16 79.38 0 top
C4502  SCD1U16V2KX-3GP  [C402H22]  98.22 76.87 90 bottom
C5301  SC1U10V2KX-1GP  [C402H22]  18.72 76.87 0 top
C5302  SCD1U16V2KX-3DLGP  [C402H22]  16.33 76.2 270 top
C5303  SC10U6D3V3MX-GP  [C603H38]  20.5 77.34 270 top
C5304  SCD1U16V2KX-3GP  [C402H22]  22.51 80.79 90 top
C5501  SC100P50V2JN-3GP  [C402H22]  19.46 23.27 90 top
C5502  SC1U50V3KX-GP  [C603H32]  26.38 16.31 270 bottom
C5503  SCD1U25V2KX-GP  [C402H22]  26.34 17.37 270 bottom
C5504  SC4D7U25V5KX-GP  [C805H54]  25.13 27.01 270 top
C5505  SCD01U50V2KX-1GP  [C402H22]  23.72 31.51 90 top
C5506  SC100P50V2JN-3GP  [C402H22]  27.85 18.86 90 top
C5507  SC5P50V2CN-2GP  [C402H22]  60.17 17.98 90 top
C5508  SC5P50V2CN-2GP  [C402H22]  62.08 17.98 270 top
C5509  SCD47U25V3KX-1GP  [C603H36]  11.45 27.76 90 top
C5510  SCD1U25V2KX-GP  [C402H22]  18.42 33.6 180 top
C5511  SC1U50V3KX-GP  [C603H32]  15.47 34.6 180 top
C5512  SCD1U25V2KX-GP  [C402H22]  17.53 34.19 180 top
C5513  SC5P50V2CN-2GP  [C402H22]  57.51 16.97 90 top
C5514  SC5P50V2CN-2GP  [C402H22]  59.41 16.97 270 top
C5515  SC1KP50V2KX-1GP  [C402H22]  19.34 33.6 180 top
C5516  SC5P50V2CN-2GP  [C402H22]  54.71 18.03 90 top
C5517  SC5P50V2CN-2GP  [C402H22]  56.62 18.03 270 top
C5518  SC5P50V2CN-2GP  [C402H22]  49.17 18.03 90 top
C5519  SC5P50V2CN-2GP  [C402H22]  51.08 18.03 270 top
C5520  SCD01U50V2KX-1GP  [C402H22]  23.73 29.57 90 top
C5521  SC5P50V2CN-2GP  [C402H22]  52.27 17.12 90 top
C5522  SC5P50V2CN-2GP  [C402H22]  54.18 17.12 270 top
C5523  SC5P50V2CN-2GP  [C402H22]  46.74 16.69 90 top
C5524  SC5P50V2CN-2GP  [C402H22]  48.64 16.69 270 top
C5525  SC5P50V2CN-2GP  [C402H22]  44.07 17.6 90 top
C5526  SC5P50V2CN-2GP  [C402H22]  45.97 17.6 270 top
C5527  SC1U10V2KX-1GP  [C402H22]  32.39 15.82 90 top
C5528  SCD1U16V2KX-3GP  [C402H22]  32.4 16.73 90 top
C5529  SC5P50V2CN-2GP  [C402H22]  41.73 16.76 90 top
C5530  SC5P50V2CN-2GP  [C402H22]  43.64 16.71 270 top
C5531  SC5P50V2CN-2GP  [C402H22]  35.97 16.76 90 top
C5532  SC5P50V2CN-2GP  [C402H22]  37.87 16.76 270 top
C5533  SC5P50V2CN-2GP  [C402H22]  38.58 15.85 90 top
C5534  SC5P50V2CN-2GP  [C402H22]  40.49 15.85 270 top
C5536  SC10U25V5KX-GP  [C805H56]  23.87 23.47 90 top
C5537  SC1U100V6KX-GP  [C1206H71]  15.29 18.74 90 bottom
C5538  SC1U100V6KX-GP  [C1206H71]  15.29 16.55 90 bottom
C5539  SC1U100V6KX-GP  [C1206H71]  20.39 15.42 270 bottom
C5540  SC1U100V6KX-GP  [C1206H71]  20.4 13.1 270 bottom
C5541  SC10U25V5KX-GP  [C805H56]  23.92 21.41 90 top
C5542  SC1U100V6KX-GP  [C1206H71]  20.29 17.74 270 bottom
C5544  SC330P100V3JN-GP  [C603H36]  15.99 21.13 270 bottom
C5545  SCD1U16V2KX-3GP  [C402H22]  64.62 20.78 270 bottom
C5550  SC10U6D3V3MX-GP  [C603H38]  67.16 14.94 90 bottom
C5551  SCD1U16V2KX-3GP  [C402H22]  66.92 13.88 90 bottom
C5554  SC1U10V2KX-1GP  [C402H22]  68.6 23.41 90 bottom
C5556  SC22U6D3V3MX-1-GP  [C603H40]  66.97 20.81 90 bottom
C5559  SCD1U16V2KX-3GP  [C402H22]  64.57 21.73 270 bottom
C5601  SCD1U16V2KX-3GP  [C402H22]  37.39 19.76 0 bottom
C5602  SCD1U16V2KX-3GP  [C402H22]  36.44 19.77 0 bottom
C5603  SCD1U16V2KX-3GP  [C402H22]  34.63 19.81 0 bottom
C5604  SCD1U16V2KX-3GP  [C402H22]  35.57 19.81 0 bottom
C5605  SCD1U16V2KX-3GP  [C402H22]  32.82 19.81 0 bottom
C5606  SCD1U16V2KX-3GP  [C402H22]  33.76 19.81 0 bottom
C5607  SCD1U16V2KX-3GP  [C402H22]  58.77 15.32 180 bottom
C5608  SC10U25V5KX-GP  [C805H56]  32.91 20.81 270 top
C5609  SCD1U16V2KX-3GP  [C402H22]  36.42 22.12 270 top
C5610  SCD1U16V2KX-3GP  [C402H22]  36.42 23.02 270 top
C5611  SC10U6D3V3MX-GP  [C603H38]  29.22 29.01 180 top
C5612  SCD1U16V2KX-3GP  [C402H22]  30.26 29.01 180 top
C5613  SCD1U16V2KX-3GP  [C402H22]  32.75 24.83 90 top
C5614  SCD1U16V2KX-3GP  [C402H22]  32.75 25.7 90 top
C5615  SCD1U16V2KX-3GP  [C402H22]  32.54 27.8 90 top
C5616  SC22U6D3V3MX-1-GP  [C603H40]  32.93 26.78 90 top
C5617  SC10U25V5KX-GP  [C805H56]  33.67 23.41 90 top
C5618  SCD1U16V2KX-3GP  [C402H22]  29.27 19.37 0 top
C5619  SCD1U16V2KX-3GP  [C402H22]  30.15 19.37 0 top
C5620  SCD1U16V2KX-3GP  [C402H22]  41.5 23.98 180 bottom
C5621  SC4D7U6D3V2MX-GP-U  [C402-TO0D2H26]  28.05 24.61 180 bottom
C5701  SCD1U16V2KX-3GP  [C402H22]  64.82 26.84 270 top
C5702  SCD1U16V2KX-3GP  [C402H22]  64.82 27.73 270 top
C5703  SCD1U16V2KX-3GP  [C402H22]  64.84 23.21 270 top
C5704  SCD1U16V2KX-3GP  [C402H22]  64.84 22.32 270 top
C5705  SCD1U16V2KX-3GP  [C402H22]  64.82 25.42 270 top
C5707  SCD1U16V2KX-3GP  [C402H22]  64.82 24.5 270 top
C5708  SCD1U16V2KX-3GP  [C402H22]  64.82 28.9 270 top
C5709  SCD1U16V2KX-3GP  [C402H22]  64.82 29.79 270 top
C5713  SC470P50V2KX-3GP  [C402H22]  62.24 55.71 0 top
C5714  SCD1U16V2KX-3GP  [C402H22]  61.04 51.99 180 top
C5721  SCD1U16V2KX-3GP  [C402H22]  56.37 59.68 180 top
C5722  SCD1U16V2KX-3GP  [C402H22]  56.37 56.93 0 top
C6001  SCD1U16V2KX-3GP  [C402H22]  13.37 76.44 90 top
C6002  SC10U25V5KX-GP  [C805H56]  14.18 77.86 90 top
C6003  SCD01U50V2KX-1GP  [C402H22]  12.83 53.06 270 top
C6004  SCD01U50V2KX-1GP  [C402H22]  12.83 53.95 270 top
C6005  SCD01U50V2KX-1GP  [C402H22]  12.82 56.12 270 top
C6006  SCD01U50V2KX-1GP  [C402H22]  12.82 55.22 270 top
C6101  SCD1U16V2KX-3GP  [C402H22]  141.81 16.43 0 bottom
C6102  SCD1U16V2KX-3GP  [C402H22]  140.92 16.43 0 bottom
C6103  SC10P50V2JN-4GP  [C402H22]  133.93 12.5 90 top
C6104  SC10U6D3V3MX-GP  [C603H38]  132.92 6.93 90 bottom
C6105  SCD1U25V2KX-GP  [C402H22]  132.95 4.6 0 top
C6106  SCD1U25V2KX-GP  [C402H22]  133.85 4.62 0 top
C6107  SCD1U25V2KX-GP  [C402H22]  131.77 21.09 270 top
C6108  SC10U6D3V3MX-GP  [C603H38]  131.74 23.04 270 top
C6109  SCD1U25V2KX-GP  [C402H22]  131.76 21.99 270 top
C6301  SC10P50V2JN-4GP  [C402H22]  82.18 70.51 0 top
C6303  SCD1U16V2KX-3GP  [C402H22]  86.51 62.12 0 top
C6304  SC10U6D3V3MX-GP  [C603H38]  84.2 61.9 0 top
C6305  SCD1U16V2KX-3GP  [C402H22]  85.7 76.15 0 top
C6306  SCD22U10V2KX-L1-GP  [C402H22]  91.12 68.13 90 bottom
C6307  SCD22U10V2KX-L1-GP  [C402H22]  91.12 69.02 90 bottom
C6308  SCD22U10V2KX-L1-GP  [C402H22]  89.92 71.28 90 bottom
C6309  SCD22U10V2KX-L1-GP  [C402H22]  89.92 72.17 90 bottom
C6310  SCD22U10V2KX-L1-GP  [C402H22]  90.37 74.18 90 bottom
C6311  SCD22U10V2KX-L1-GP  [C402H22]  90.37 75.07 90 bottom
C6331  SCD22U10V2KX-L1-GP  [C402H22]  91.19 77.75 90 bottom
C6332  SCD22U10V2KX-L1-GP  [C402H22]  91.19 78.64 90 bottom
C6341  SCD1U16V2KX-3GP  [C402H22]  85.62 62.13 0 top
C6342  SC10U6D3V3MX-GP  [C603H38]  83.15 75.96 0 top
C6345  SCD1U16V2KX-3GP  [C402H22]  84.68 76.15 0 top
C6401  SCD01U50V2KX-1GP  [C402H22]  124.21 7.17 270 top
CAM1  ACES-CON8-78-GP  [51290-0084N-W01]  217 101.6 180 top
CMOS1  SW-TACT-4P-60-GP-U  [SKRBAJF010]  260.62 22.1 270 top
CNVBD1  ACES-CON12-49-GP  [51290-0124N-W01]  15 4.5 180 top
CPU1  ICE-LAKE-U-GP-U  [BGA1526M2550-1H51]  181.37 48.8 180 top
CRS1  CARDBUS11P-SKT-7-GP  [156-5001902601]  31.5 94.7 180 top
D2401  AZ5125-02S-R7G-GP  [SOT23-2D4-312H46]  94.06 26.2 0 bottom
D2402  AZ5125-02S-R7G-GP  [SOT23-2D4-312H46]  70.47 29.39 270 bottom
D2403  AZ5125-02S-R7G-GP  [SOT23-2D4-312H46]  97.35 29.62 270 top
D2501  BAT54C-11-GP  [SOT23-2D4-312H44]  166.92 11.82 180 bottom
D2701  AZ5125-02S-R7G-GP  [SOT23-2D4-312H46]  39.98 65.5 90 top
D3101  RB551V30-GP  [SOD323AKH38]  57.7 68.76 90 top
D3102  AZ5125-01H-R7G-GP  [SOD-523-4H28]  60.47 63.39 90 bottom
D4004  BAT54C-11-GP  [SOT23-2D4-312H44]  179.37 7.34 180 bottom
D4005  BAT54C-11-GP  [SOT23-2D4-312H44]  183.39 7.34 180 bottom
D4302  BAV70W-1-GP  [SOT-323H40]  76.9 54.67 180 bottom
D5301  1SS355-4-GP  [SOD323AKH38]  138.55 31.55 90 top
D5501  BX310F-R1-00000-GP  [D4724AKH44]  14.27 13.74 270 bottom
D5701  BAW56-9-GP-U  [SOT23-2D4-312H44]  58.88 58.24 270 top
D6301  AZ5725-01FDR7G-GP  [SOD882-10D6-1H20]  83.84 70.51 0 top
D6903  AZ5725-01FDR7G-GP  [SOD882-10D6-1H20]  215.76 11.77 180 bottom
D6904  AZ5725-01FDR7G-GP  [SOD882-10D6-1H20]  84.23 20.84 180 bottom
DBGH1  ACES-CON14-11-GP  [50228-0147N-W01]  105.37 21.8 90 top
DCIN1  DC-JACK361-GP  [2DC3012-005111F]  89 41.05 180 top
DIMM1  DDR4-260P-74-GP  [ASAA821-E8RB0-7H]  252 42.3 270 top
DIMM2  DDR4-260P-114-GP  [ASAA821-H4RB5-7H]  237 42.3 270 top
EC1720  SC22P50V2JN-L-GP  [C402H22]  216.69 11.82 180 bottom
EC1801  SC22P50V2JN-4GP  [C402H22]  104.13 6.15 0 bottom
EC1802  SC22P50V2JN-4GP  [C402H22]  104.13 8.86 180 bottom
EC2902  SC1KP50V2KX-1GP  [C402H22]  6.16 13.57 270 bottom
EC2903  SC1KP50V2KX-1GP  [C402H22]  6.16 14.46 270 bottom
EC2904  SC1KP50V2KX-1GP  [C402H22]  7.08 15.57 90 bottom
EC2905  SC1KP50V2KX-1GP  [C402H22]  7.08 16.53 90 bottom
EC2909  SC1KP50V2KX-L-1-GP  [C402H22]  11.7 43.95 90 top
EC2910  SC1KP50V2KX-L-1-GP  [C402H22]  17.9 47.02 270 top
EC2911  SC1KP50V2KX-L-1-GP  [C402H22]  13.09 48 90 top
EC2912  SC1KP50V2KX-L-1-GP  [C402H22]  19.86 47.01 270 top
EC2913  SC1KP50V2KX-L-1-GP  [C402H22]  13.08 47.11 90 top
EC3101  SC6P50V2CN-1GP  [C402H22]  74.49 72.28 90 top
EC3102  SC6P50V2CN-1GP  [C402H22]  72.56 72.28 270 top
EC3103  SC6P50V2CN-1GP  [C402H22]  68.44 72.35 90 top
EC3104  SC6P50V2CN-1GP  [C402H22]  66.49 72.35 270 top
EC3105  SC6P50V2CN-1GP  [C402H22]  71.47 71.4 90 top
EC3106  SC6P50V2CN-1GP  [C402H22]  69.55 71.41 270 top
EC3107  SC6P50V2CN-1GP  [C402H22]  65.38 71.47 90 top
EC3108  SC6P50V2CN-1GP  [C402H22]  63.43 71.47 270 top
EC3321  SC5P50V2CN-2GP  [C402H22]  20.19 89.92 90 bottom
EC3322  SC5P50V2CN-2GP  [C402H22]  24.26 89.92 270 bottom
EC3323  SC5P50V2CN-2GP  [C402H22]  22.23 89.92 90 bottom
EC3324  SC5P50V2CN-2GP  [C402H22]  41.66 89.28 270 bottom
EC3325  SC5P50V2CN-2GP  [C402H22]  39.24 89.28 270 bottom
EC3326  SC5P50V2CN-2GP  [C402H22]  28 89.15 90 bottom
EC3327  SC5P50V2CN-2GP  [C402H22]  36.96 89.28 270 bottom
EC3328  SC5P50V2CN-2GP  [C402H22]  43.94 89.28 270 bottom
EC4301  SC1U50V3KX-GP  [C603H32]  83.48 44.15 90 bottom
EC4302  SCD1U50V3KX-GP  [C603H36]  83.47 45.44 90 bottom
EC5501  SC1KP50V2KX-1GP  [C402H22]  25.48 10.45 90 bottom
EC5502  SC1KP50V2KX-1GP  [C402H22]  25.29 11.59 90 bottom
EC5503  SC1KP50V2KX-1GP  [C402H22]  24.94 12.68 90 bottom
EC6401  SC1KP50V2KX-1GP  [C402H22]  123.92 5.5 90 top
EC6402  SC1KP50V2KX-1GP  [C402H22]  111.16 3.36 90 top
EC6901  SCD1U25V2KX-GP  [C402H22]  26.41 26.52 270 bottom
EC6902  SCD1U25V2KX-GP  [C402H22]  81.06 43.06 0 bottom
EC6903  SCD1U25V2KX-GP  [C402H22]  67.69 35.8 0 bottom
EC6904  SCD1U25V2KX-GP  [C402H22]  84.93 46.52 90 bottom
EC6905  SCD1U25V2KX-GP  [C402H22]  80.12 43.05 0 bottom
EC6906  SCD1U16V2KX-3GP  [C402H22]  39.26 82.2 270 top
EC6907  SCD1U16V2KX-3GP  [C402H22]  43.17 62.11 90 top
EC6908  SCD1U16V2KX-3GP  [C402H22]  14.53 82.02 180 top
EC6909  SCD1U16V2KX-3GP  [C402H22]  50.86 64.43 180 top
EC6910  SCD1U16V2KX-3GP  [C402H22]  45.2 77.07 270 bottom
EC6913  SCD1U16V2KX-3GP  [C402H22]  78.83 72.89 90 top
EC6914  SCD1U16V2KX-3GP  [C402H22]  85.74 59.82 180 top
EC6915  SCD1U16V2KX-3GP  [C402H22]  68.62 23.4 270 top
EC6916  SCD1U16V2KX-3GP  [C402H22]  82.1 56.79 0 top
EC6917  SCD1U16V2KX-3GP  [C402H22]  81.21 56.8 0 top
EC6918  SCD1U25V2KX-GP  [C402H22]  74.44 40.4 45 bottom
EC6919  SCD1U25V2KX-GP  [C402H22]  84.94 47.41 90 bottom
EC6920  SCD1U25V2KX-GP  [C402H22]  70.48 36.47 45 bottom
EC6921  SCD1U25V2KX-GP  [C402H22]  73.1 39.05 45 bottom
EC6922  SCD1U25V2KX-GP  [C402H22]  66.8 35.81 0 bottom
EC6923  SCD1U25V2KX-GP  [C402H22]  74.68 42.93 90 bottom
ECIO1  IT8637E-BX-GP  [LQFP128H63]  82.2 17.18 180 top
ED2901  AZ5125-02S-R7G-GP  [SOT23-2D4-312H46]  6.38 24.09 0 bottom
ED2902  AZ5125-02S-R7G-GP  [SOT23-2D4-312H46]  12.09 23.42 180 bottom
ED2903  AZ5125-02S-R7G-GP  [SOT23-2D4-312H46]  19.02 49.44 270 top
ED2904  AZ5125-02S-R7G-GP  [SOT23-2D4-312H46]  12.27 50.57 0 top
ED2905  AZ5125-02S-R7G-GP  [SOT23-2D4-312H46]  10.07 46.43 90 top
ED3002  ESD5345E-6-TR-GP  [SOT-6H58]  226.19 98.92 270 top
ED3101  LBAV99LT1G-1-GP  [SOT23-2D4-312H44]  56.62 64.14 270 bottom
ED3102  LBAV99LT1G-1-GP  [SOT23-2D4-312H44]  58.94 68.21 270 bottom
ED3103  LBAV99LT1G-1-GP  [SOT23-2D4-312H44]  62.94 68.24 180 bottom
ED3401  ESD5345E-6-TR-GP  [SOT-6H58]  45.52 29.13 0 top
ED3402  AZ1043-04F-R7G-GP  [DFN10G2510H22]  28.84 53.83 90 top
ED3403  AZ1043-04F-R7G-GP  [DFN10G2510H22]  45.63 52.74 0 top
ED3501  AZ1043-04F-R7G-GP  [DFN10G2510H22]  187.08 88.6 180 top
ED3502  ESD5345E-6-TR-GP  [SOT-6H58]  201.7 94.81 180 bottom
ED3504  AZ1043-04F-R7G-GP  [DFN10G2510H22]  52.98 89.68 0 bottom
ED3505  ESD5345E-6-TR-GP  [SOT-6H58]  55.41 88.69 270 top
ED4301  P6SMBJ20A-GP-U  [DO214AAAK-1121H97]  93.69 48.92 270 top
ED5701  AZ1043-04F-R7G-GP  [DFN10G2510H22]  55.39 24.93 90 top
ED5702  AZ1043-04F-R7G-GP  [DFN10G2510H22]  55.49 28.87 270 top
ED5703  AZC099-04S-2-GP  [SOT-6H58]  45.31 56.46 180 bottom
ED6001  AZ1043-04F-R7G-GP  [DFN10G2510H22]  9.72 54.58 270 top
ED6101  ESD5345E-6-TR-GP  [SOT-6H58]  141.5 29.81 90 bottom
ED6902  AZ5725-01FDR7G-GP  [SOD882-10D6-1H20]  59.81 89.85 0 top
EL3001  DUMMY-FILTER-4P-132-GP  [DUMMY-LD65D85-4PH20]  229.87 99.25 180 top
EL3401  DUMMY-FILTER-4P-132-GP  [DUMMY-LD65D85-4PH20]  48.38 24.46 270 top
EL3402  DUMMY-FILTER-4P-132-GP  [DUMMY-LD65D85-4PH20]  50.28 26.6 270 top
EL3403  FILTER-4P-98-GP  [L125100-4P-5H24]  25.62 52.66 90 top
EL3404  FILTER-4P-98-GP  [L125100-4P-5H24]  25.62 55.17 90 top
EL3405  FILTER-4P-98-GP  [L125100-4P-5H24]  43.91 56.52 0 top
EL3406  FILTER-4P-98-GP  [L125100-4P-5H24]  46.1 56.49 0 top
EL3501  FILTER-4P-98-GP  [L125100-4P-5H24]  181.36 86.18 90 top
EL3502  FILTER-4P-98-GP  [L125100-4P-5H24]  181.62 88.36 90 top
EL3503  DUMMY-FILTER-4P-132-GP  [DUMMY-LD65D85-4PH20]  203.3 100.15 90 top
EL3507  FILTER-4P-98-GP  [L125100-4P-5H24]  51.88 86.38 0 bottom
EL3508  FILTER-4P-98-GP  [L125100-4P-5H24]  54.02 86.36 0 bottom
EL3509  DUMMY-FILTER-4P-132-GP  [DUMMY-LD65D85-4PH20]  51.37 89.25 90 top
EL5701  FILTER-4P-98-GP  [L125100-4P-5H24]  59.66 25.53 270 top
EL5702  FILTER-4P-98-GP  [L125100-4P-5H24]  59.65 23.36 270 top
EL5703  FILTER-4P-98-GP  [L125100-4P-5H24]  59.65 27.73 270 top
EL5704  FILTER-4P-98-GP  [L125100-4P-5H24]  59.64 29.92 270 top
EL6001  FILTER-4P-98-GP  [L125100-4P-5H24]  16.86 54.34 90 top
EL6002  FILTER-4P-98-GP  [L125100-4P-5H24]  16.79 57.32 90 top
EL6103  DUMMY-FILTER-4P-132-GP  [DUMMY-LD65D85-4PH20]  145.18 29.22 270 bottom
ER1801  0R0402-PAD-2-GP  [0R0402-PAD-1]  172.99 20.71 0 top
ER1802  0R0402-PAD-2-GP  [0R0402-PAD-1]  171.95 20.71 0 top
F3001  POLYSW-1D1A6V-9-GP-U  [POLYSW-2114H30]  224.39 99.62 180 bottom
F3002  POLYSW-1D1A6V-9-GP-U  [POLYSW-2114H30]  209.14 99.19 90 top
F5501  POLYSW-1D1A24V-GP-U  [POLYSW-4633-UH43]  24.21 21.3 90 bottom
F5701  POLYSW-1D1A6V-9-GP-U  [POLYSW-2114H30]  60.05 55.08 270 top
F6001  POLYSW-2A6V-7-GP  [POLYSW-2114H30]  14.14 79.94 270 top
FANC1  ETY-CON3-5-GP  [3801-Q03S-01R]  261.5 7 270 top
FC9001  SC18P50V2JN-1-GP  [C402H22]  184.94 36.34 180 bottom
FC9002  SC18P50V2JN-1-GP  [C402H22]  186.93 43.38 180 bottom
FC9003  SC18P50V2JN-1-GP  [C402H22]  176.28 47.59 90 bottom
FC9004  SC18P50V2JN-1-GP  [C402H22]  176.28 46.53 90 bottom
FC9005  SC18P50V2JN-1-GP  [C402H22]  176.28 45.36 90 bottom
FC9006  SC18P50V2JN-1-GP  [C402H22]  176.28 44.14 90 bottom
FC9007  SC18P50V2JN-1-GP  [C402H22]  176.85 68.31 0 bottom
FC9008  SC18P50V2JN-1-GP  [C402H22]  172.17 64.82 90 bottom
FC9009  SC18P50V2JN-1-GP  [C402H22]  177.7 64.33 270 bottom
FC9010  SC18P50V2JN-1-GP  [C402H22]  177.71 68.31 0 bottom
FC9011  SC18P50V2JN-1-GP  [C402H22]  176.07 60.5 270 bottom
FC9012  SC18P50V2JN-1-GP  [C402H22]  176.08 59.61 270 bottom
FC9085  SCD1U25V2KX-GP  [C402H22]  247.81 64.45 270 bottom
FC9086  SCD1U25V2KX-GP  [C402H22]  247.81 63.14 270 bottom
FC9087  SCD1U25V2KX-GP  [C402H22]  247.99 52.78 270 bottom
FC9088  SCD1U25V2KX-GP  [C402H22]  256.09 54.72 180 bottom
FC9089  SCD1U25V2KX-GP  [C402H22]  255.77 50.77 0 bottom
FC9090  SCD1U25V2KX-GP  [C402H22]  252.44 51.5 180 bottom
FC9091  SCD1U25V2KX-GP  [C402H22]  191.76 52.29 90 bottom
FC9092  SCD1U25V2KX-GP  [C402H22]  241.6 13.37 180 bottom
G2401  COPPER-CLOSE-GP-U  [CON2C-U]  72.39 28.87 0 top
G2530  GAP-OPEN  [CON2O-U]  262.22 26.22 180 top
G6401  COPPER-CLOSE-GP-U  [CON2C-U]  118.75 15.21 0 top
GDT1  P4500SCLHLRP-GP  [TVS5436-1121H105]  63.53 58.67 180 bottom
H1  GEN315R158-8-F-C-S-GP-U  [GEN315R158-8-F-C-S-U]  5 100.3 180 top
H2  GEN315R158-8-F-C-S-GP-U  [GEN315R158-8-F-C-S-U]  115.39 80.5 180 top
H3  GEN315R158-8-F-C-S-GP-U  [GEN315R158-8-F-C-S-U]  102.69 41.9 180 top
H4  GEN315R158-8-F-C-S-GP-U  [GEN315R158-8-F-C-S-U]  250 100.3 180 top
H5  GEN315R158-8-F-C-S-GP-U  [GEN315R158-8-F-C-S-U]  6 36.9 180 top
HDMI1  SKT-HDMI22-19-GP  [SKT-HDMI22-148070]  54 41.04 270 top
HS5  STF256R109H124-GP  [STF256R109H124]  110.91 13.05 180 top
HS6  STF256R113-UH286-1-GP  [STF256R113-UH286]  12.4 71.4 180 top
HS7  STF236R128H34-1-GP  [STF236R128H34]  50.4 71.4 180 top
L2401  MHC1005P121ZBP2A0-GP  [L402-TO0D2H24]  68.69 28.49 180 top
L2903  MHC1005P121ZBP2A0-GP  [L402-TO0D2H24]  22.22 70.69 270 top
L2904  MHC1005P121ZBP2A0-GP  [L402-TO0D2H24]  4.19 18.75 180 bottom
L2905  MHC1005P121ZBP2A0-GP  [L402-TO0D2H24]  5.4 18.75 180 bottom
L2906  MHC1005P121ZBP2A0-GP  [L402-TO0D2H24]  9.73 19.58 180 bottom
L2907  MHC1005P121ZBP2A0-GP  [L402-TO0D2H24]  8.56 19.58 180 bottom
L2910  MHC1005P121ZBP2A0-GP  [L402-TO0D2H24]  22.46 69.51 270 top
L3101  IND-4D7UH-326-GP-U  [L3030-3009-2H40]  67.73 88.59 0 bottom
L3102  COIL-90OHM-100MHZ-5-GP  [L125100-4P-4H24]  64.39 73.52 90 top
L3103  COIL-90OHM-100MHZ-5-GP  [L125100-4P-4H24]  67.42 74.32 90 top
L3104  COIL-90OHM-100MHZ-5-GP  [L125100-4P-4H24]  70.51 73.38 90 top
L3105  COIL-90OHM-100MHZ-5-GP  [L125100-4P-4H24]  73.55 74.29 90 top
L3301  COIL-90OHM-100MHZ-5-GP  [L125100-4P-4H24]  38.59 90.85 180 bottom
L3302  MHC1005P121ZBP2A0-GP  [L402-TO0D2H24]  30.86 95 270 bottom
L5501  MCM1012B900FBP-GP-U  [L125100-4P-1H37]  20.99 28.54 90 bottom
L5502  IND-33UH-85-GP  [L8080-6020H158]  21.14 15.86 270 top
L5601  HCB1005KF-600T25-GP  [L402H24]  57.68 15.31 180 bottom
L5602  HCB1005KF-600T25-GP  [L402H24]  60.02 13.86 90 bottom
L6401  MHC1608S601LBP-GP  [L603H38]  112.26 6.74 90 top
L6405  MHC1005P121ZBP2A0-GP  [L402-TO0D2H24]  126.33 5.96 90 top
L6406  MHC1005P121ZBP2A0-GP  [L402-TO0D2H24]  116.61 12.14 0 top
LAN1  RTL8111G-CGT-1-GP-U2  [QFN32J4-G2D85H36]  62.38 84.11 0 bottom
LED1  LED-OW-8-GP  [LED3020-3P-6H44]  117 2.05 180 top
LED683  LED-YG-51-GP-U  [LED1608-1A2KH40]  8.26 89.1 270 top
LED684  LED-YG-51-GP-U  [LED1608-1A2KH40]  8.3 91.8 270 top
LED685  LED-YG-51-GP-U  [LED1608-1A2KH40]  8.02 86.41 90 top
LVDS1  ACES-CON30-23-GP  [50524-0300N-001]  44.5 8.3 0 top
MFG1  SW-SLIDE3P-11-GP  [MSS3-Q-T-R]  206.1 8.27 90 bottom
NGFFE1  SKT-NGFF75P-91-GP  [AS0BC21-S40BE-7H]  139.16 13 270 top
NGFFM1  SKT-NGFF75P-217-GP  [APCI0096-P003A]  90 71.4 270 top
NOREF  -  []  186.84 63.83 90 top
NOREF#2  -  []  186.84 63.83 90 top
NOREF#3  -  []  202.97 99.9 90 top
NOREF#4  -  []  168.87 23.8 0 top
NOREF#5  -  []  174.41 34.29 0 top
NOREF#6  -  []  209.68 74.55 0 top
NOREF#7  -  []  202.28 99.23 90 top
NOREF#8  -  [unnamed#2]  161.82 35.57 0 top
NOREF#9  -  []  144.86 28.97 90 top
NOREF#10  -  []  170.88 43.44 90 top
NOREF#11  -  []  50.35 88.32 90 top
NOREF#12  -  []  42.44 47.44 90 top
NOREF#13  -  []  195.87 75.8 90 top
NOREF#14  -  []  195.87 129.8 0 top
NOREF#15  -  []  50.35 88.32 0 top
NOREF#16  -  []  32.34 37.04 90 top
NOREF#17  -  []  199.87 141.8 0 top
NOREF#18  -  [unnamed#2]  71.15 101.37 0 top
NOREF#19  -  []  37.49 59.56 0 top
NOREF#20  -  []  176.72 31.77 90 top
NOREF#21  -  [unnamed#2]  259.84 110.72 0 top
NOREF#22  -  []  144.17 30.15 0 top
NOREF#23  -  []  -9.34 -8.05 0 top
NOREF#24  -  []  237 7.9 90 top
NOREF#25  -  []  42.44 34.64 90 top
NOREF#26  -  []  178.9 63.83 0 top
NOREF#27  -  []  30.94 47.44 90 top
NOREF#28  -  []  0 0 0 top
NOREF#29  -  []  186.84 37.95 90 top
NOREF#30  *  [unnamed#2]  41.59 79.59 0 top
NOREF#31  -  []  51.29 25.68 90 top
